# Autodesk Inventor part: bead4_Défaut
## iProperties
Shininess: 64.0
Length Units: 11269
Angle Units: 11279
Time Units: 11290
Mass Units: 11283
Length Display Precision: 3
Angle Display Precision: 2
Compacted: True
Part Number: bead4_Défaut
Document SubType Name: Modeling
Created: 2006-11
Material: Par défaut
Designer: profs_sti
Density: 0.0
Volumn: 0.0
Area: 0.0
PropertySet Name: Model Information
Control State: 0
Master: False
Checked Out: False
Author: profs_sti
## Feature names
1. Base1
